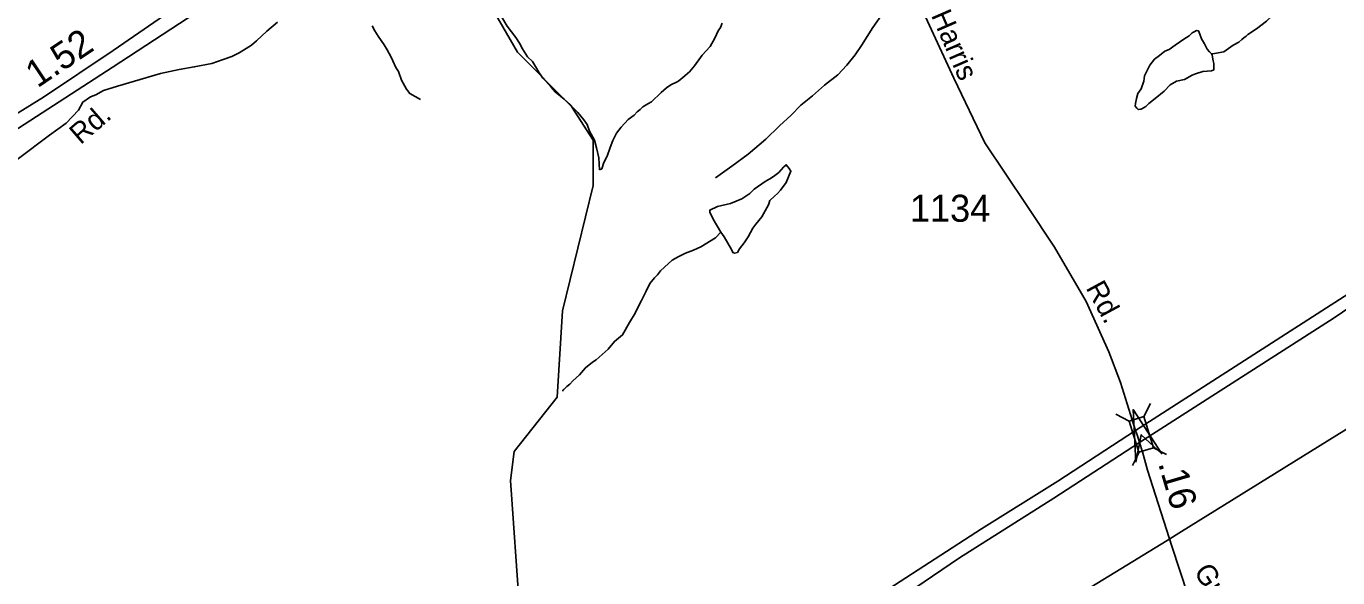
# Model space of a CAD drawing. Extents: x 2001466 to 2224147, y 644118 to 847247.
# Drawn here: x 2011219 to 2017291, y 695087 to 697641 of the extents above; entities that cross this region are included whole.
import ezdxf

# ---------------------------------------------------------------- set-up
doc = ezdxf.new("R2010")
doc.units = 0
for name, color, linetype in [('Exist Hydrographic Creek Single Shore', 7, 'Continuous'), ('Exist Hydrographic Misc Water Feature', 7, 'Continuous'), ('Exist Railroad Mainline', 7, 'Continuous'), ('Exist Road Non-System Type 51', 7, 'Continuous'), ('Exist Road Non-System Type 51 Label', 7, 'Continuous'), ('Exist Road Primary US Divided Attributed', 7, 'Continuous'), ('Exist Road Secondary Mileage Hundredths English Label', 7, 'Continuous'), ('Exist Road Secondary Structure Standard Bridge Attributed CELL', 7, 'Continuous'), ('Exist Road Secondary Structure Standard Bridge CELL', 7, 'Continuous'), ('Exist Road Secondary Type 51 Attributed', 7, 'Continuous'), ('Exist Road Secondary Type 51 Label', 7, 'Continuous'), ('Exist Road Secondary Type 51 Number Label', 7, 'Continuous'), ('Exist Utilities Electrical Transmission Line', 7, 'Continuous')]:
    doc.layers.add(name, color=color, linetype=linetype)

msp = doc.modelspace()

# ---------------------------------------------------------------- linework, layer by layer
at = {"layer": 'Exist Hydrographic Creek Single Shore'}
msp.add_lwpolyline([(2013834, 693635.4), (2013837.4, 693737.2), (2013795.4, 694072.7), (2013770.4, 694096.2), (2013703.5, 694504.4), (2013586.4, 694720.1), (2013503.4, 694944.9), (2013461.6, 695536.4), (2013477.6, 695670.6), (2013677.5, 695922.4), (2013702.5, 696322.2), (2013843.6, 696903.4), (2013843.6, 697113.4), (2013743.5, 697269.6), (2013493.6, 697520.8), (2013334.6, 697796.3), (2013284.6, 697945), (2013292.6, 698154.8), (2013434.5, 698404.6), (2013567.6, 698503.6), (2013717.7, 698681), (2013925.6, 698811.3), (2014425.5, 698870)], dxfattribs=at)
at = {"layer": 'Exist Hydrographic Misc Water Feature'}
msp.add_line((2013704.1, 695955.1), (2013704.1, 695951.1), dxfattribs=at)
for points in [[(2016706.7, 697512.8), (2016720.9, 697514.8), (2016762.7, 697522.8), (2016806.8, 697552.8), (2016832.8, 697566.8), (2016846.8, 697578.9), (2016856.8, 697586.9), (2016866.9, 697594.9), (2016874.9, 697602.9), (2016914.6, 697628.9), (2016960.6, 697664.9), (2016992.6, 697692.9), (2017026.6, 697716.9), (2017054.7, 697732.9), (2017070.7, 697737), (2017098.6, 697746.9), (2017114.6, 697759), (2017140.6, 697769), (2017186.5, 697785.1), (2017234.5, 697791.1), (2017266.7, 697791.1), (2017290.5, 697791.1)], [(2013421.2, 697682.7), (2013445.2, 697640.7), (2013485.1, 697588.7), (2013503.2, 697562.7), (2013517.1, 697536.7), (2013539.3, 697498.8), (2013563.3, 697476.8), (2013581.3, 697446.8), (2013593.2, 697424.8), (2013601.2, 697414.8), (2013611.3, 697400.8), (2013621.3, 697388.9), (2013649.4, 697358.9), (2013667.2, 697336.9), (2013709.3, 697302.9), (2013737.4, 697278.9), (2013753.4, 697260.9), (2013773.4, 697241), (2013801.3, 697207), (2013815.5, 697185), (2013827.4, 697155), (2013849.3, 697113), (2013859.4, 697077), (2013869.6, 697031.1), (2013871.5, 697003), (2013873.5, 696975.1)], [(2013873.5, 696975.1), (2013883.6, 696981.1), (2013893.6, 697009), (2013909.4, 697039.1), (2013923.3, 697079.1), (2013935.4, 697111.1), (2013951.4, 697145), (2013973.4, 697173.1), (2014005.4, 697209.1), (2014033.5, 697229.1), (2014047.2, 697245.1), (2014061.3, 697255.2), (2014073.2, 697267.2), (2014097.2, 697281.1), (2014113.2, 697291.2), (2014159.4, 697333.2), (2014183.3, 697355.2), (2014203.2, 697369.2), (2014233.4, 697383.2), (2014241.2, 697387.3), (2014259.2, 697403.3), (2014289.2, 697429.2), (2014313.1, 697457.3), (2014341.2, 697495.3), (2014349.2, 697507.3), (2014385.1, 697547.3), (2014407.1, 697585.3), (2014423.1, 697619.3), (2014433.1, 697635.3), (2014441.1, 697655.3)], [(2016706.7, 697512.8), (2016708.8, 697508.8), (2016710.8, 697496.8), (2016714.7, 697480.8), (2016717, 697468.8), (2016717, 697450.8), (2016717, 697438.7), (2016706.9, 697434.7), (2016666.9, 697430.7), (2016632.9, 697420.7), (2016616.9, 697414.7), (2016580.8, 697394.7), (2016544.9, 697386.7), (2016515, 697368.7), (2016486.9, 697340.7), (2016445.1, 697306.6), (2016417, 697282.6), (2016403, 697268.6), (2016390.9, 697262.6), (2016381.1, 697256.6), (2016377, 697256.6), (2016366.9, 697254.6), (2016361, 697260.6), (2016353, 697270.5), (2016355.1, 697282.5), (2016359, 697306.6), (2016365.1, 697328.6), (2016380.9, 697350.6), (2016393, 697386.6), (2016396.9, 697410.6), (2016410.8, 697438.6), (2016420.9, 697460.6), (2016442.8, 697488.6), (2016465, 697504.6), (2016490.8, 697524.6), (2016510.9, 697532.6), (2016538.8, 697552.7), (2016578.8, 697580.7), (2016602.8, 697596.7), (2016616.7, 697610.7), (2016628.8, 697616.7), (2016636.8, 697620.7), (2016646.8, 697618.8), (2016652.8, 697604.7), (2016660.8, 697582.7), (2016674.7, 697558.7), (2016686.8, 697534.7), (2016696.7, 697522.8), (2016706.7, 697512.8)], [(2014435.6, 696687.5), (2014399.5, 696747.4), (2014389.4, 696767.4), (2014383.5, 696777.4), (2014383.5, 696789.4), (2014419.6, 696805.4), (2014479.4, 696819.5), (2014531.5, 696841.5), (2014569.5, 696865.5), (2014589.6, 696885.5), (2014639.4, 696921.5), (2014661.3, 696933.6), (2014679.4, 696945.6), (2014703.4, 696963.6), (2014725.3, 696987.6), (2014737.4, 696999.6), (2014751.3, 696981.6), (2014759.3, 696969.6), (2014737.4, 696917.6), (2014711.4, 696881.6), (2014697.6, 696865.6), (2014683.5, 696853.6), (2014661.5, 696833.6), (2014655.6, 696813.6), (2014625.4, 696757.5), (2014597.6, 696723.5), (2014583.6, 696705.5), (2014561.7, 696665.5), (2014543.6, 696637.5), (2014531.7, 696623.5), (2014521.7, 696609.5), (2014511.6, 696593.5), (2014497.7, 696589.5), (2014489.7, 696593.5), (2014483.5, 696607.5), (2014449.7, 696665.4), (2014435.6, 696687.5)], [(2014435.6, 696687.5), (2014409.7, 696661.4), (2014341.6, 696619.4), (2014307.6, 696603.4), (2014271.7, 696589.4), (2014237.7, 696573.3), (2014209.8, 696557.3), (2014173.7, 696525.3), (2014155.7, 696507.3), (2014141.7, 696489.2), (2014127.8, 696475.2), (2014105.8, 696449.3), (2014087.8, 696411.3), (2014067.9, 696371.3), (2014051.9, 696341.2), (2014038, 696311.3), (2014011.9, 696269.3), (2013979.9, 696211.2), (2013942, 696181.2), (2013913.9, 696145.2), (2013857.9, 696095.1), (2013840.1, 696085.1), (2013808.1, 696059.1), (2013780.2, 696027.1), (2013750.1, 695999.1), (2013736.1, 695983.1), (2013722.2, 695973.1), (2013714.2, 695965.1), (2013708.2, 695959.1), (2013704.1, 695955.1)]]:
    msp.add_lwpolyline(points, dxfattribs=at)
at = {"layer": 'Exist Railroad Mainline'}
msp.add_lwpolyline([(2008026.4, 695106.9), (2008808.3, 695617.7), (2009285.1, 695939.5), (2010611.9, 696800.1), (2011617.7, 697449.9), (2013634.7, 698769.2), (2014695.2, 699465.6)], dxfattribs=at)
at = {"layer": 'Exist Road Non-System Type 51'}
for points in [[(2015269.4, 697856), (2015185.7, 697702.5), (2015137.9, 697634.5), (2015086, 697552.3), (2015056.3, 697508.3), (2015018.3, 697460.1), (2014976.4, 697416.1), (2014914.6, 697368), (2014858.8, 697317.7), (2014804.7, 697275.6), (2014761, 697229.5), (2014707.2, 697179.4), (2014643.3, 697117.3), (2014561.5, 697049), (2014485.6, 696992.9), (2014409.8, 696938.6)], [(2012382.4, 697659.6), (2012332.6, 697617.4), (2012284.6, 697573.3), (2012262.8, 697553.2), (2012236.7, 697537.1), (2012204.9, 697517.2), (2012171, 697501.1), (2012130.9, 697486.9), (2012078.9, 697468.7), (2011997, 697452.6), (2011927.1, 697440.4), (2011841.1, 697422.2), (2011721.2, 697386), (2011641.3, 697363.6), (2011577.3, 697343.5), (2011541.5, 697323.5), (2011517.5, 697313.3), (2011481.6, 697289.3), (2011462, 697252.4), (2011404, 697191.6), (2011326.7, 697136.3), (2011177.6, 697023)], [(2013044.3, 697301.9), (2012994.8, 697329.1), (2012980, 697348.9), (2012957, 697391), (2012942.8, 697430.9), (2012930.8, 697449), (2012916.8, 697480.9), (2012909.4, 697498.2), (2012890.9, 697531.6), (2012876, 697555.1), (2012848.8, 697594.7), (2012832.4, 697620.2), (2012821.4, 697642.3)]]:
    msp.add_lwpolyline(points, dxfattribs=at)
at = {"layer": 'Exist Road Primary US Divided Attributed'}
for points in [[(2019927.7, 698050.8), (2019711.5, 697929.8), (2019611.8, 697868.6), (2019488.3, 697791.6), (2019234.1, 697619.4), (2018843.7, 697362.1), (2018321.8, 697033.1), (2018196.5, 696955.5), (2018051.3, 696858.8), (2017678.1, 696619), (2016354.4, 695769)], [(2016373.5, 695712.3), (2017274, 696290), (2017463.2, 696417.8), (2017697.5, 696558.6), (2018092.1, 696817.1), (2018220.2, 696897.8), (2019245.1, 697555.7), (2019599.3, 697775.8), (2019809, 697909.2), (2019890.4, 697959.1)], [(2016354.4, 695769), (2015995.6, 695534.5), (2015641.4, 695312.8), (2015211.9, 695035), (2014351, 694485.4), (2014145.9, 694354.7), (2013691.2, 694062.6), (2013587.9, 693999), (2013367.8, 693854.8), (2012886, 693550.6), (2012194.3, 693097.4), (2011972.2, 692956), (2011644.8, 692748.7), (2011338.8, 692562.9), (2011067, 692388.7), (2010845.9, 692261.9), (2010157.6, 691873.1), (2010003.9, 691785.1), (2009218.8, 691345.2)], [(2009248.4, 691292), (2010017.6, 691725), (2010186.5, 691819.4), (2010841.9, 692187.2), (2011116.9, 692345.3), (2011367, 692502.3), (2012056.8, 692944.6), (2012186.4, 693025.1), (2012896.1, 693486), (2013510.3, 693873.6), (2014154.8, 694289.4), (2014322.1, 694397.2), (2014335.8, 694406.3), (2015251.3, 694982.5), (2015539.1, 695179.1), (2015976.9, 695455.1), (2016373.5, 695712.3)]]:
    msp.add_lwpolyline(points, dxfattribs=at)
at = {"layer": 'Exist Road Secondary Structure Standard Bridge Attributed CELL'}
msp.add_lwpolyline([(2016356.1, 695621.7), (2016343.2, 695865.2), (2016476.1, 695660.7), (2016381, 695749.2)], close=True, dxfattribs=at)
at = {"layer": 'Exist Road Secondary Structure Standard Bridge CELL'}
for p, q in [((2016424.2, 695894.2), (2016392.4, 695832.9)), ((2016263.9, 695843.5), (2016325.1, 695811.7)), ((2016437.5, 695688.7), (2016498.7, 695656.9)), ((2016371.7, 695668), (2016339.9, 695606.8))]:
    msp.add_line(p, q, dxfattribs=at)
msp.add_lwpolyline([(2016392.4, 695832.9), (2016437.9, 695688.8), (2016370.5, 695667.6), (2016325.1, 695811.7)], close=True, dxfattribs=at)
at = {"layer": 'Exist Road Secondary Type 51 Attributed'}
for points in [[(2014527.7, 699935.1), (2014412, 699805.8), (2014282.8, 699666.9), (2014121.3, 699520.8), (2013846.8, 699277.3), (2013542.5, 699006.7), (2013193.1, 698696.2), (2012860.1, 698400.8), (2012730, 698289.9), (2012554.6, 698173.3), (2012326.4, 698013.7), (2012022.9, 697806.9), (2011621.6, 697528.3), (2011299, 697312), (2010853, 697037.4), (2010490.5, 696826.7), (2010122.7, 696626.3), (2009741.8, 696387.6), (2009328.6, 696149.7), (2008976.4, 695945.4), (2008497, 695667.6), (2007991.2, 695369.8)], [(2016354.4, 695769), (2016285.2, 695990.7), (2016231.6, 696133.6), (2016126.4, 696365.9), (2015979.2, 696617.6), (2015852.2, 696810.4), (2015656.5, 697100.5), (2015512.9, 697400.6), (2015175.4, 698133.4), (2014933.7, 698657.1), (2014869.9, 698837.5), (2014757.4, 699297.3), (2014711.8, 699476.5)], [(2016373.5, 695712.3), (2016363.2, 695743.6), (2016354.4, 695769)], [(2016633.2, 694894.4), (2016523.3, 695232.5), (2016410.6, 695585.3), (2016386.2, 695669.5), (2016373.5, 695712.3)]]:
    msp.add_lwpolyline(points, dxfattribs=at)
at = {"layer": 'Exist Utilities Electrical Transmission Line'}
for points in [[(2018205.4, 696316.2), (2016567.8, 695300.4), (2016501.7, 695259.9)], [(2016501.7, 695259.9), (2015960.7, 694928.7), (2013834, 693635.4)]]:
    msp.add_lwpolyline(points, dxfattribs=at)

# ---------------------------------------------------------------- texts
at = {"layer": 'Exist Road Non-System Type 51 Label'}
msp.add_text('Rd.', height=95, rotation=40.75669, dxfattribs=at).set_placement((2011470.6, 697089.4))
at = {"layer": 'Exist Road Secondary Mileage Hundredths English Label'}
for s, rotation, p in [('1.52', 33.83877, (2011270.7, 697352.3)), ('.16', 286.31505, (2016458.3, 695616.6))]:
    msp.add_text(s, height=125, rotation=rotation, dxfattribs=at).set_placement(p)
at = {"layer": 'Exist Road Secondary Type 51 Label'}
for s, rotation, p in [('Harris', 293.48964, (2015406.9, 697691.9)), ('Rd.', 298.43313, (2016122.6, 696429.3)), ('Gunter-Morris', 301.87015, (2016622, 695116))]:
    msp.add_text(s, height=95, rotation=rotation, dxfattribs=at).set_placement(p)
at = {"layer": 'Exist Road Secondary Type 51 Number Label'}
msp.add_text('1134', height=125, dxfattribs=at).set_placement((2015310.3, 696735.3))

doc.saveas('drawing.dxf')
